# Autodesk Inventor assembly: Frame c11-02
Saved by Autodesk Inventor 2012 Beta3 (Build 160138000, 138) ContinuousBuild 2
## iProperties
Created: 2011-01
Part Number: Frame c11-02
Document SubType Name: Assembly
Designer: Beta-8540w
_FrameDoc: Frame Assembly
_Version: 15.0.0
Author: Beta-8540w
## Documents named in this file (16)
- C:\Inventor 2012 Essentials\Assemblies\Chapter 11\Frame\Frame c11-02.iam
- C:\Inventor 2012 Essentials\Assemblies\Chapter 11\Frame\Skeleton-c11-02.ipt
- C:\Inventor 2012 Essentials\Assemblies\Chapter 11\Frame\ANSI 3x3x3_16 00000001.ipt
- ANSI 3x3x3_16 00000001.ipt
- C:\Inventor 2012 Essentials\Assemblies\Chapter 11\Frame\ANSI 3x3x3_16 00000002.ipt
- ANSI 3x3x3_16 00000002.ipt
- C:\Inventor 2012 Essentials\Assemblies\Chapter 11\Frame\ANSI 3x3x3_16 00000003.ipt
- ANSI 3x3x3_16 00000003.ipt
- C:\Inventor 2012 Essentials\Assemblies\Chapter 11\Frame\ANSI 3x3x3_16 00000004.ipt
- ANSI 3x3x3_16 00000004.ipt
- C:\Inventor 2012 Essentials\Assemblies\Chapter 11\Frame\ANSI 3x3x3_16 00000005.ipt
- ANSI 3x3x3_16 00000005.ipt
- C:\Inventor 2012 Essentials\Assemblies\Chapter 11\Frame\ANSI 3x3x3_16 00000006.ipt
- ANSI 3x3x3_16 00000006.ipt
- C:\Inventor 2012 Essentials\Assemblies\Chapter 11\Frame\ANSI L 1.5 x 1.5 x 3_16 00000007.ipt
- ANSI L 1.5 x 1.5 x 3_16 00000007.ipt
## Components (8 placed, 8 different names)
1. Frame Reference Model
2. ANSI 3x3x3_16 00000001:1
3. ANSI 3x3x3_16 00000002:1
4. ANSI 3x3x3_16 00000003:1
5. ANSI 3x3x3_16 00000004:1
6. ANSI 3x3x3_16 00000005:1
7. ANSI 3x3x3_16 00000006:1
8. ANSI L 1.5 x 1.5 x 3_16 00000007:1
